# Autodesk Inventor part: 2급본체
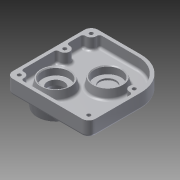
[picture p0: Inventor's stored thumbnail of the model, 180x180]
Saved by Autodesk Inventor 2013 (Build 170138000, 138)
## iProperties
Created: 2015-11
Part Number: 2급본체
Material: 알루미늄 6061
Document SubType Name: Modeling
Designer: Administrator
Density: 1 g/cm^3
Author: Administrator
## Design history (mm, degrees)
sketch "스케치1"
  geometry: L1 (-44.906, -34.091)-(39.094, -34.091); L2 (47.094, -26.091)-(47.094, 28.909); L3 (7.094, 68.909)-(-44.906, 68.909); L4 (-52.906, 60.909)-(-52.906, -26.091); A1 r 40 centre (7.094, 28.909) between (47.094, 28.909) and (7.094, 68.909); A2 r 8 centre (-44.906, 60.909) between (-44.906, 68.909) and (-52.906, 60.909); A3 r 8 centre (-44.906, -26.091) between (-52.906, -26.091) and (-44.906, -34.091); A4 r 8 centre (39.094, -26.091) between (39.094, -34.091) and (47.094, -26.091); 4 further points
  constraints: 8 end point, 8 point on circle, 8 tangent, 6 point on line, 4 centre point, 2 equal radius, 2 parallel, 1 horizontal, 1 perpendicular
  dimensions: "d0" = 103 distance of point (-52.906, 68.909) point (-52.906, -34.091); "d2" = 100 distance of point (-52.906, -34.091) point (47.094, -34.091); "d3" = 40 radius of A1; "d4" = 8 radius of A2
extrude "돌출1" new body sketch "스케치1" distance "d5" = 18; taper "d6" = 0 deg
sketch "스케치2"
  geometry: L1 (47.094, -26.091)-(47.094, 28.909) reference; L2 (7.094, 68.909)-(-44.906, 68.909) reference; L3 (-52.906, 60.909)-(-52.906, -26.091) reference; L4 (-44.906, -34.091)-(39.094, -34.091) reference; A1 r 40 centre (7.094, 28.909) between (47.094, 28.909) and (7.094, 68.909) reference; A2 r 8 centre (-44.906, 60.909) between (-44.906, 68.909) and (-52.906, 60.909) reference; A3 r 8 centre (-44.906, -26.091) between (-52.906, -26.091) and (-44.906, -34.091) reference; A4 r 8 centre (39.094, -26.091) between (39.094, -34.091) and (47.094, -26.091) reference; 1 further point
feature "쉘1" dims "d9" = 4
sketch "스케치3"
  geometry: L1 (88, 4)-(88, 59) reference; L2 (52, 95)-(0, 95) reference; L3 (-4, 91)-(-4, 4) reference; L4 (0, 0)-(84, 0) reference; L5 (84, -4)-(0, -4) reference; L6 (-8, 4)-(-8, 91) reference; L7 (0, 99)-(52, 99) reference; L8 (92, 59)-(92, 4) reference; L9 (0, 59)-(84, 59); C1 r 6 at (0, 91); C2 r 6 at (0, 4); C3 r 6 at (0, 59); C4 r 6 at (84, 59); C5 r 6 at (84, 4); A1 r 4 centre (0, 91) between (0, 95) and (-4, 91) reference; A2 r 4 centre (0, 4) between (-4, 4) and (0, 0) reference; A3 r 4 centre (84, 4) between (84, 0) and (88, 4) reference; A4 r 36 centre (52, 59) between (88, 59) and (52, 95) reference; A5 r 4 centre (0, 91) between (0, 95) and (-4, 91) reference; A6 r 4 centre (0, 4) between (-4, 4) and (0, 0) reference; A7 r 8 centre (84, 4) between (84, -4) and (92, 4) reference; A8 r 8 centre (0, 4) between (-8, 4) and (0, -4) reference; A9 r 8 centre (0, 91) between (0, 99) and (-8, 91) reference; A10 r 40 centre (52, 59) between (92, 59) and (52, 99) reference; 1 further point
  constraints: 5 centre point, 4 coincident, 2 end point, 1 perpendicular
  dimensions: "d10" = 12 diameter of C1; "d12" = 6 radius of C2; "d14" = 6 radius of C3; "d15" = 84 distance of L9.start L9.end; "d16" = 6 radius of C4; "d17" = 6 radius of C5
extrude "돌출2" join sketch "스케치3" distance "d18" = 14; taper "d19" = 0 deg
fillet "모깎기2" dims "d21" = 3
fillet "모깎기3" dims "d22" = 3
sketch "스케치4"
  geometry: L1 (0, 89)-(43.056, 89) reference; L2 (-9.944, 64.944)-(-9.944, 79.056) reference; L3 (-9.944, 9.944)-(-9.944, 47.056) reference; L4 (66.111, 0)-(0, 0) reference; L5 (76.056, 47.056)-(76.056, 9.944) reference; A1 r 33 centre (43.056, 56) between (74.806, 64.997) and (43.056, 89) reference; A2 r 9 centre (-8.944, 88) between (-9.944, 79.056) and (0, 89) reference; A3 r 9 centre (-8.944, 56) between (-9.944, 47.056) and (-9.944, 64.944) reference; A4 r 9 centre (-8.944, 1) between (0, 0) and (-9.944, 9.944) reference; A5 r 9 centre (75.056, 1) between (76.056, 9.944) and (66.111, 0) reference; A6 r 9 centre (75.056, 56) between (74.806, 64.997) and (76.056, 47.056) reference; 1 further point
sketch "스케치5"
  geometry: L1 (0, 89)-(43.056, 89) reference; L2 (-9.944, 64.944)-(-9.944, 79.056) reference; L3 (-9.944, 9.944)-(-9.944, 47.056) reference; L4 (66.111, 0)-(0, 0) reference; L5 (76.056, 47.056)-(76.056, 9.944) reference; A1 r 33 centre (43.056, 56) between (74.806, 64.997) and (43.056, 89) reference; A2 r 9 centre (-8.944, 88) between (-9.944, 79.056) and (0, 89) reference; A3 r 9 centre (-8.944, 56) between (-9.944, 47.056) and (-9.944, 64.944) reference; A4 r 9 centre (-8.944, 1) between (0, 0) and (-9.944, 9.944) reference; A5 r 9 centre (75.056, 1) between (76.056, 9.944) and (66.111, 0) reference; A6 r 9 centre (75.056, 56) between (74.806, 64.997) and (76.056, 47.056) reference; 1 further point
sketch "스케치6"
  geometry: A1 r 6 centre (-44.906, -26.091) between (-38.943, -26.758) and (-45.573, -20.128) reference; A2 r 6 centre (-44.906, 28.909) between (-45.573, 22.946) and (-45.573, 34.872) reference; A3 r 6 centre (39.094, 28.909) between (38.927, 34.906) and (39.761, 22.946) reference; A4 r 8 centre (-44.906, 60.909) between (-44.906, 68.909) and (-52.906, 60.909) reference; A5 r 8 centre (39.094, -26.091) between (39.094, -34.091) and (47.094, -26.091) reference; 1 further point
hole "구멍1" sketch "스케치6" at (-44.906, 60.909), (-44.906, 28.909), (39.094, 28.909), (39.094, -26.091), (-44.906, -26.091) diameter "d23" = 4.5; stored, may be unused: countersink angle "d27" = 90 deg, drill point angle "d29" = 118 deg; dims "d24" = 6, "d25" = 4, "d26" = 2, "d28" = 8
sketch "스케치7"
  geometry: C1 r 2.25 at (-39.094, -26.091) reference; C2 r 2.25 at (44.906, 28.909) reference; C3 r 2.25 at (44.906, 60.909) reference; C4 r 2.25 at (-39.094, 28.909) reference; C5 r 2.25 at (44.906, -26.091) reference; 1 further point
hole "구멍2" sketch "스케치7" at (-39.094, 28.909), (-39.094, -26.091), (44.906, -26.091), (44.906, 28.909), (44.906, 60.909) diameter "d30" = 4.5; stored, may be unused: countersink angle "d34" = 90 deg, drill point angle "d36" = 118 deg; dims "d31" = 6, "d32" = 8, "d33" = 4.4, "d35" = 17
sketch "스케치8"
  geometry: L1 (-16.944, 88)-(-16.944, 1) reference; L2 (-8.944, -7)-(75.056, -7) reference; L3 (-16.944, 1)-(-16.944, -7); L4 (-9.944, -7)-(-16.944, -7); L5 (-16.944, -7)-(13.056, -7); L6 (13.056, -7)-(13.056, 23); L7 (13.056, 23)-(-16.944, 23); L8 (-16.944, 23)-(-16.944, -7); L9 (-16.944, -7)-(43.056, -7); L10 (43.056, -7)-(43.056, 56); L11 (43.056, 56)-(-16.944, 56); L12 (-16.944, 56)-(-16.944, -7); L13 (83.056, 1)-(83.056, 56) reference; L14 (43.056, 96)-(-8.944, 96) reference; L15 (43.056, 96)-(100.484, 96); L16 (83.056, 57.966)-(83.056, 104.748); L17 (83.056, 96)-(43.056, 96); L18 (43.056, 96)-(43.056, 56); C1 r 20 at (13.056, 23); C2 r 20 at (43.056, 56); A1 r 33 centre (43.056, 56) between (74.806, 64.997) and (43.056, 89) reference; 1 further point
  constraints: 28 end point, 6 perpendicular, 4 parallel, 2 centre point, 2 coincident, 2 collinear, 2 horizontal, 2 point on line
extrude "돌출3" join sketch "스케치8" distance "d44" = 11; taper "d45" = -10 deg
fillet "모깎기4" dims "d46" = 3
sketch "스케치9"
  geometry: C1 r 18.06 at (0, 0) reference; 1 further point
hole "구멍3" sketch "스케치9" at (0, 0) diameter "d47" = 20; stored, may be unused: countersink angle "d51" = 90 deg, drill point angle "d53" = 118 deg; dims "d48" = 6, "d49" = 32, "d50" = 9, "d52" = 50
sketch "스케치10"
  geometry: C1 r 18.06 at (0, 0) reference; 1 further point
hole "구멍4" sketch "스케치10" at (0, 0) diameter "d54" = 20; stored, may be unused: countersink angle "d58" = 90 deg, drill point angle "d60" = 118 deg; dims "d55" = 6, "d56" = 32, "d57" = 9, "d59" = 50
chamfer "모따기1" distance "d61" = 1; stored, may be unused: second distance "d62" = 2, angle "d63" = 45 deg
fillet "모깎기5" dims "d64" = 0.3
sketch "스케치11"
  geometry: C1 r 10 at (22.906, -4.091) reference; C2 r 25 at (22.906, -4.091); 1 further point
  constraints: 1 centre point, 1 coincident
  dimensions: "d65" = 25 radius of C2
extrude "돌출4" join sketch "스케치11" distance "d66" = 15; taper "d67" = -10 deg
sketch "스케치12"
  geometry: C1 r 12.645 at (0, 0) reference; C2 r 14 at (0, 0); 1 further point
  constraints: 1 centre point, 1 coincident
  dimensions: "d68" = 14 radius of C2
extrude "돌출5" cut sketch "스케치12" distance "d70" = 11; taper "d71" = 0 deg
chamfer "모따기2" distance "d72" = 1; stored, may be unused: second distance "d73" = 2, angle "d74" = 45 deg
sketch "스케치13"
  geometry: C1 r 10.705 at (0, 0) reference; C2 r 14 at (0, 0) reference; C3 r 12 at (0, 0); 1 further point
  constraints: 1 centre point, 1 coincident
  dimensions: "d75" = 24 diameter of C3
extrude "돌출6" cut sketch "스케치13" distance "d76" = 2; taper "d77" = 0 deg
fillet "모깎기6" dims "d78" = 2
fillet "모깎기7" dims "d79" = 0.3
sketch "스케치14" dims "d80" = 36
  geometry: C1 r 15 at (0, 0) reference; 3 further points
  constraints: 1 coincident, 1 vertical alignment, 2 other
hole "구멍5" sketch "스케치14" at (0, 18) diameter "d81" = 2.459; stored, may be unused: countersink angle "d85" = 90 deg, drill point angle "d87" = 118 deg; dims "d82" = 8, "d83" = 28, "d84" = 11, "d86" = 10
sketch "스케치15"
  geometry: L1 (52.906, -26.091)-(52.906, 60.909) reference; L2 (44.906, 68.909)-(-7.094, 68.909) reference; 2 further points
  constraints: 1 other
  dimensions: "d91" = 40 distance from line of L1 point (12.906, 48.909); "d92" = 20 distance from line of point (12.906, 48.909) L2
feature "엠보싱1" sketch "스케치15" dims "d0" = 103, "d2" = 100, "d3" = 40, "d4" = 8, "d93" = 0.5, "d94" = 0
fillet "모깎기8" dims "d95" = 3
fillet "모깎기9" dims "d96" = 3
sketch "스케치16"
  geometry: C1 r 10 at (-7.094, 28.909) reference; C2 r 10 at (-7.094, 28.909); 1 further point
  constraints: 1 centre point, 1 coincident, 1 concentric
extrude "돌출7" join sketch "스케치16" distance "d97" = 4; taper "d98" = 0 deg
sketch "스케치17"
  geometry: C1 r 17 at (0, 0) reference; C2 r 16 at (0, 0); 1 further point
  constraints: 1 centre point, 1 coincident
  dimensions: "d99" = 32 diameter of C2
extrude "돌출8" cut sketch "스케치17" distance "d100" = 9; taper "d101" = 0 deg
node "솔리드1"
pattern_circular "원형 패턴1" dims angle "d89" = 360 deg
node "절단 모서리 투영1"
